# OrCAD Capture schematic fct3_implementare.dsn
size A
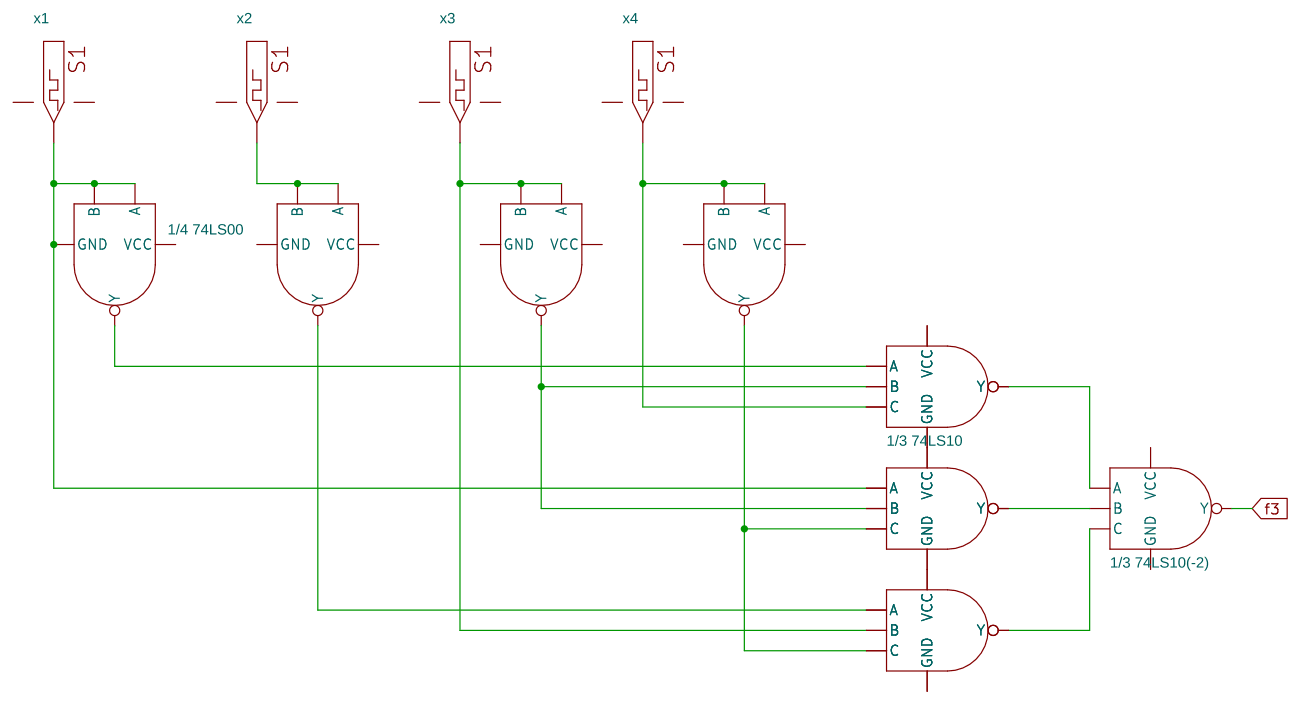
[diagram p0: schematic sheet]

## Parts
U3  1/4 74LS00  [DIP.100/14/W.300/L.800]  (section B)
U4  1/3 74LS10  [DIP.100/14/W.300/L.800]  (section A)
U5  1/4 74LS00  [DIP.100/14/W.300/L.800]  (section B)
U6  1/4 74LS00  [DIP.100/14/W.300/L.800]  (section B)
U7  1/4 74LS00  [DIP.100/14/W.300/L.800]  (section B)
U8  1/3 74LS10(-2)  [DIP.100/14/W.300/L.800]  (sections A,B,C)
x1  DigStim1
x2  DigStim1
x3  DigStim1
x4  DigStim1

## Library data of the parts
U3 U5-U7 = 74LS00
U4 U8 = 74LS10
x1-x4 = DigStim1

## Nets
GND: U3.7(GND) U4.7(GND) U5.7(GND) U6.7(GND) U7.7(GND) U8.7(GND) x1.3(GND) x2.3(GND) x3.3(GND) x4.3(GND)
VCC: U3.14(VCC) U4.14(VCC) U5.14(VCC) U6.14(VCC) U7.14(VCC) U8.14(VCC) x1.2(VCC) x2.2(VCC) x3.2(VCC) x4.2(VCC)
f3: U8.8(Y)
N14966: U3.4(A) U3.5(B) U8.1(A) x1.OUT
N14984: U5.4(A) U5.5(B) x2.OUT
N15002: U6.4(A) U6.5(B) U8.4(B) x3.OUT
N15014: U4.13(C) U7.4(A) U7.5(B) x4.OUT
N15241: U8.6(Y) U8.11(C)
N15248: U4.12(Y) U8.9(A)
N15255: U8.10(B) U8.12(Y)
N15259: U3.6(Y) U4.1(A)
N15266: U4.2(B) U6.6(Y) U8.2(B)
N15349: U7.6(Y) U8.5(C) U8.13(C)
N15356: U5.6(Y) U8.3(A)
